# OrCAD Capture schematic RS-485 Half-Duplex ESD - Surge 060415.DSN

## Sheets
1 S01 COVER PAGE AND NOTES: note: BART STILLER; note: KRYPTON SOLUTIONS
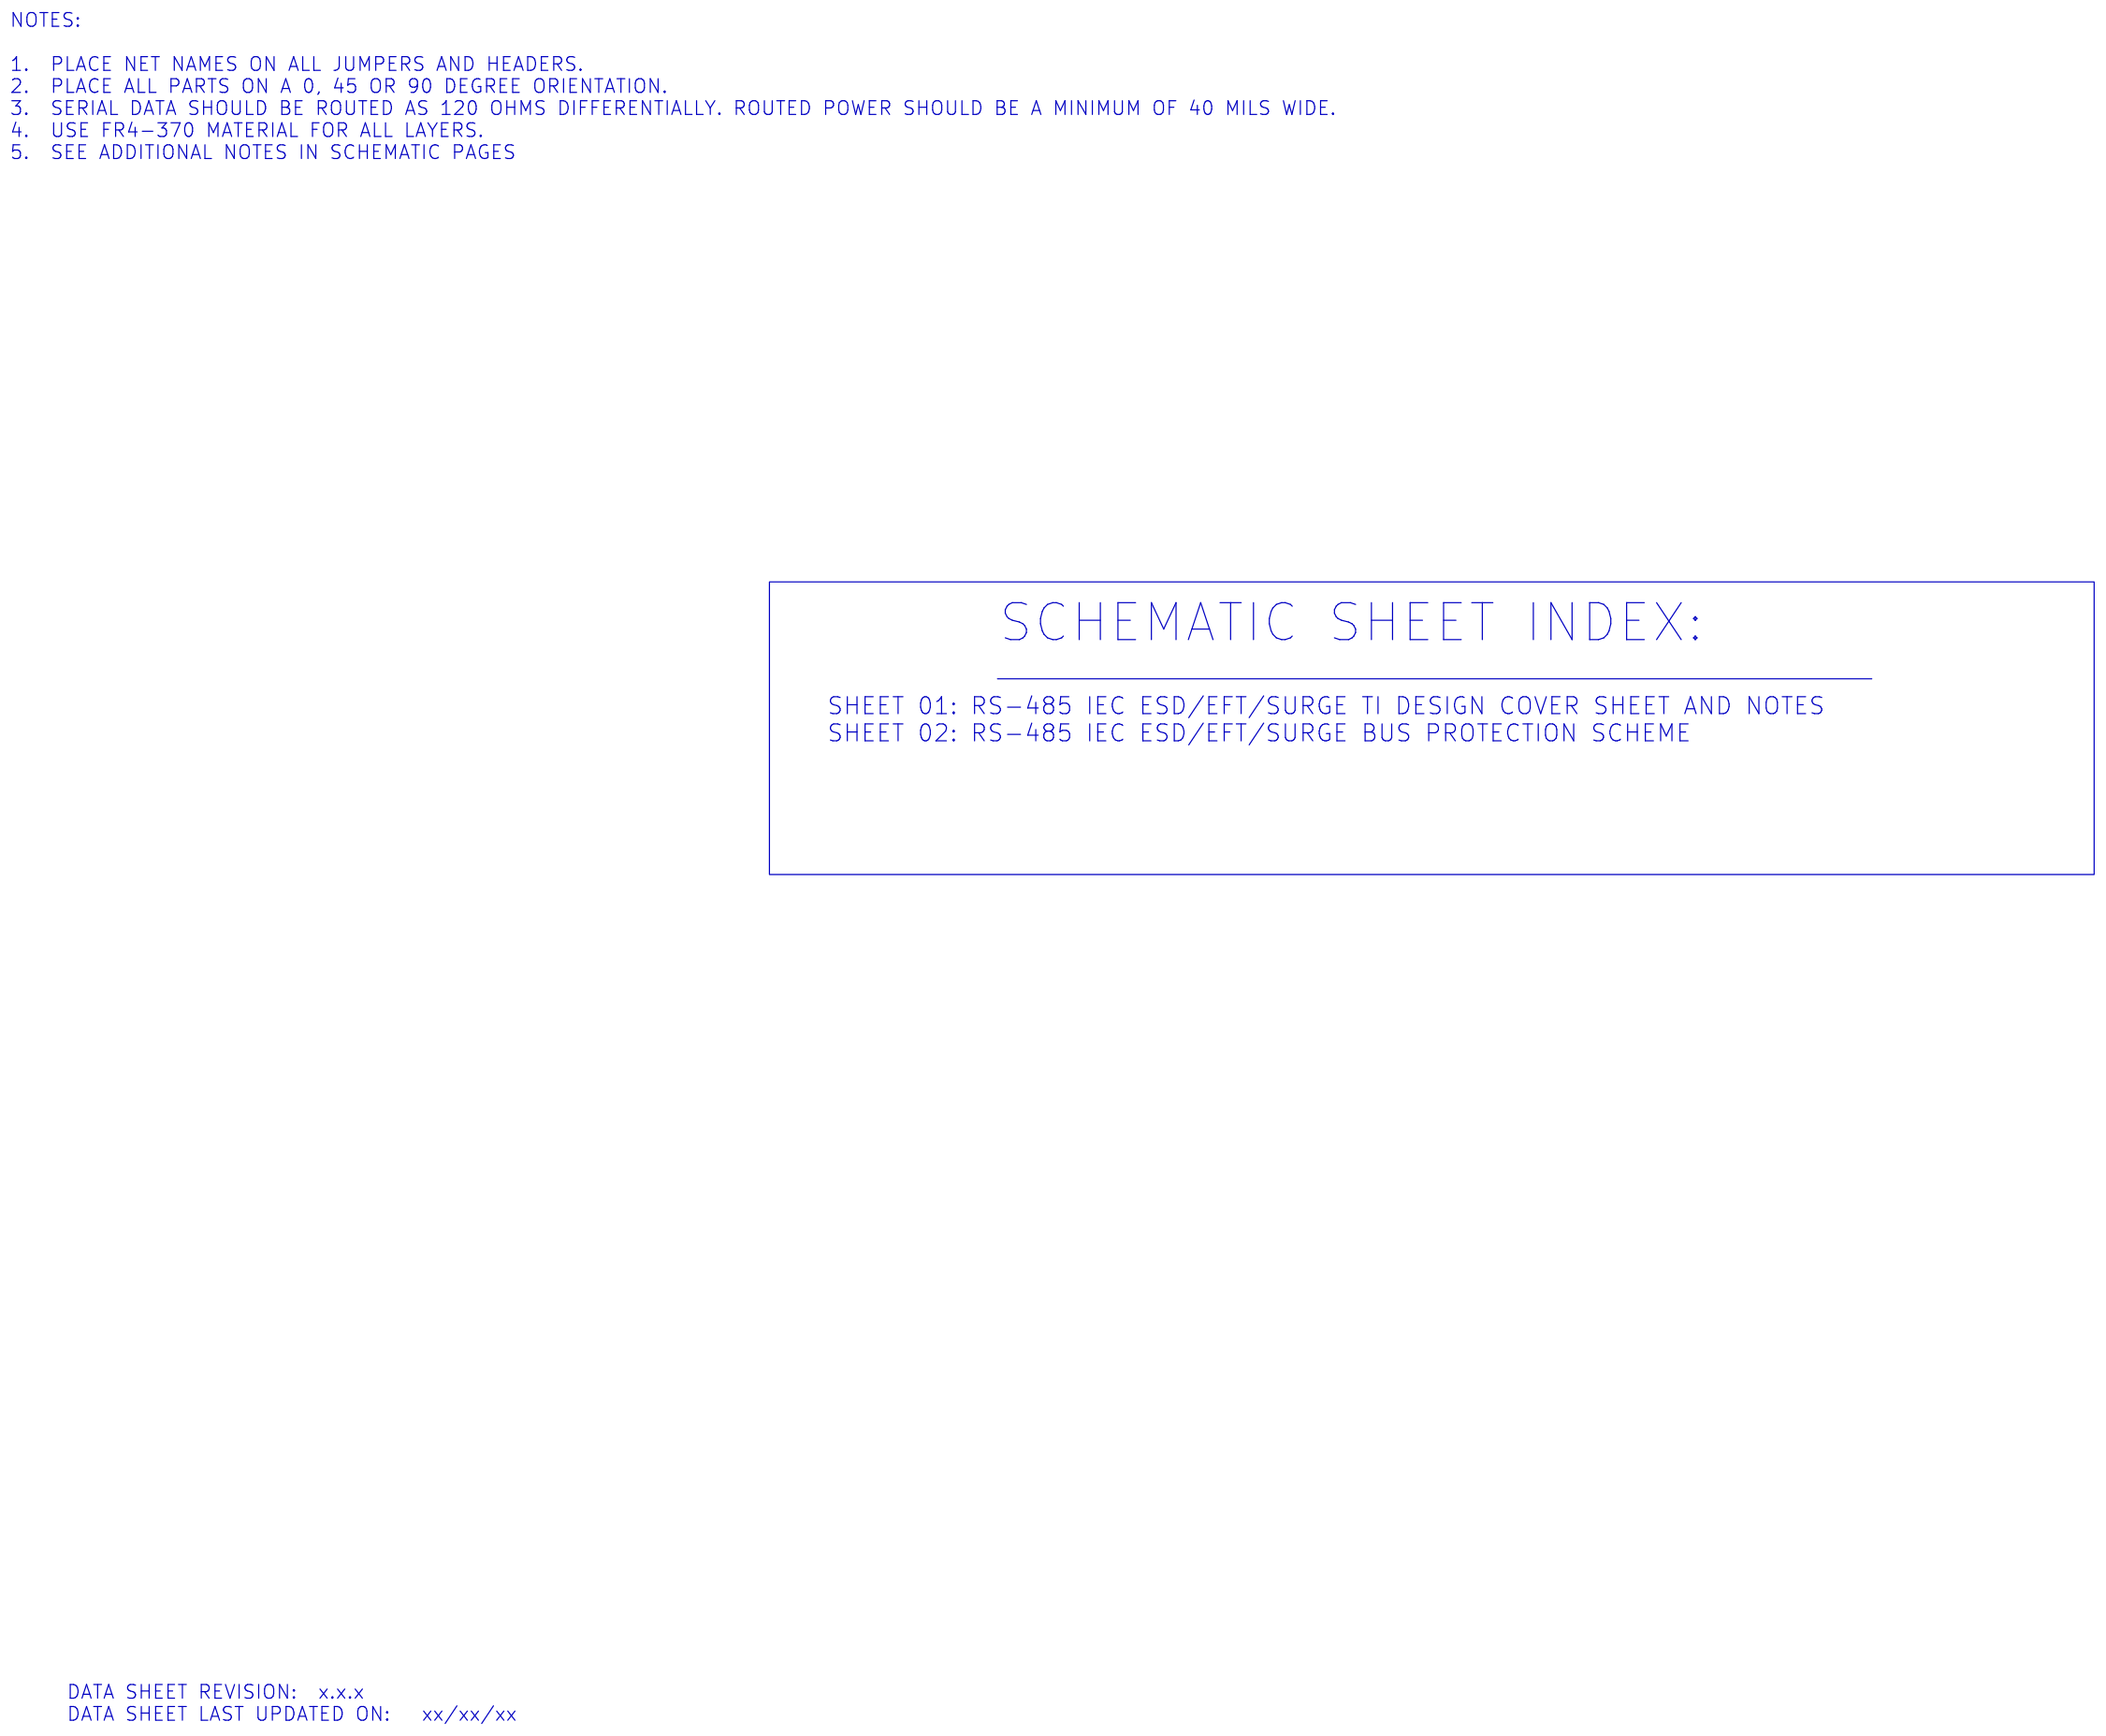
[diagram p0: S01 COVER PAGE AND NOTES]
2 S02 RS-485 SURGE SCHEMATIC: size B
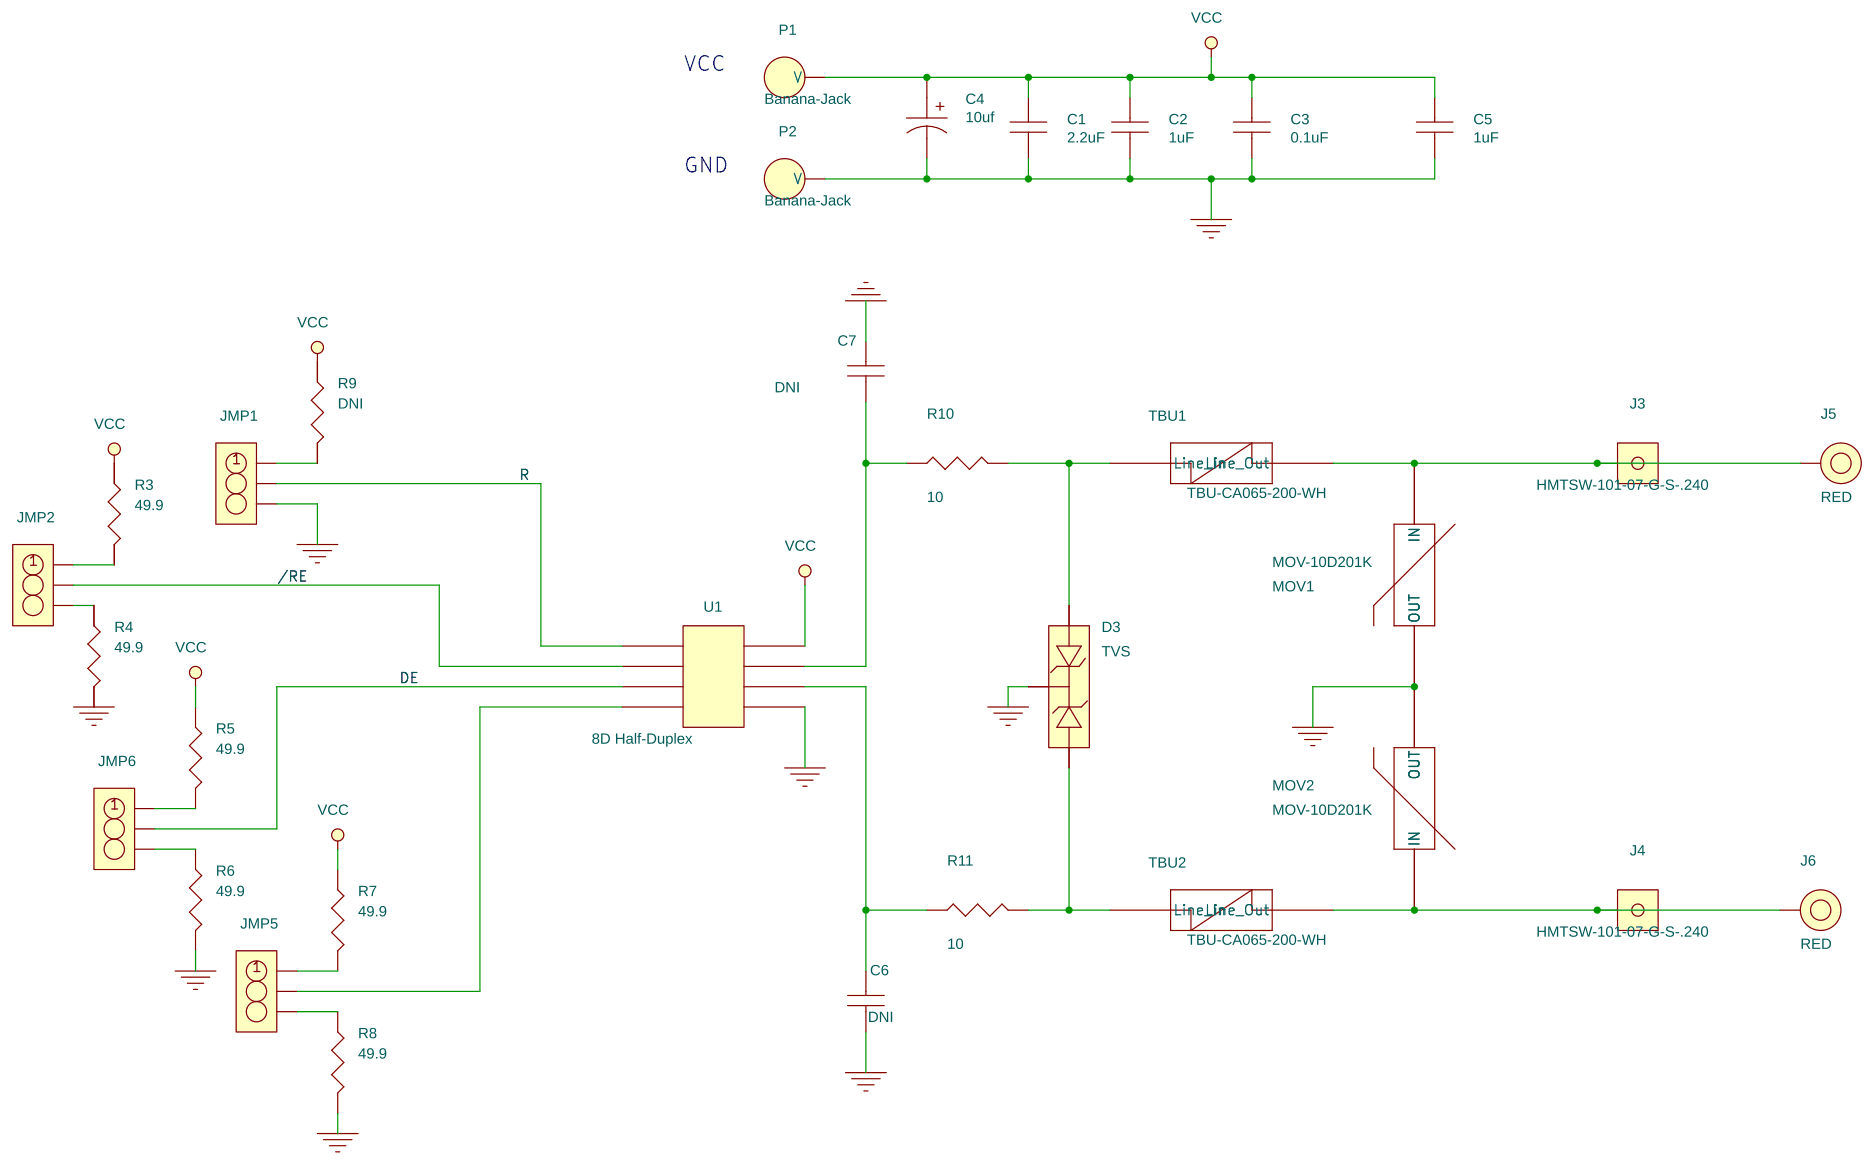
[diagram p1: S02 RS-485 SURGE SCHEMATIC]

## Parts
C1  2.2uF  [1206]
C2  1uF  [0805]
C3  0.1uF  [0603]
C4  10uf  [7343]
C5  1uF  [0402]
C6  DNI  [0603]
C7  DNI  [0603]
D3  TVS  [SOT_23_321]
J3  HMTSW-101-07-G-S-.240  [HDR_THVT_1x1]
J4  HMTSW-101-07-G-S-.240  [HDR_THVT_1x1]
J5  RED  [BANANA_JACK_270mil]
J6  RED  [BANANA_JACK_270mil]
JMP1  Header 3x1  [berg1x3]
JMP2  Header 3x1  [berg1x3]
JMP5  Header 3x1  [berg1x3]
JMP6  Header 3x1  [berg1x3]
MOV1  MOV-10D201K  [VAR_DISC_3p8x12p5mm]
MOV2  MOV-10D201K  [VAR_DISC_3p8x12p5mm]
P1  Banana-Jack  [bjack]
P2  Banana-Jack  [bjack]
R3  49.9  [0603]
R4  49.9  [0603]
R5  49.9  [0603]
R6  49.9  [0603]
R7  49.9  [0603]
R8  49.9  [0603]
R9  DNI  [0603]
R10  10  [0603]
R11  10  [0603]
TBU1  TBU-CA065-200-WH  [DFN_3_157x256]
TBU2  TBU-CA065-200-WH  [DFN_3_157x256]
U1  8D Half-Duplex  [SKT_SK02-0008SOP-QS-05A]

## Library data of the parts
C1 = NPCap1206_1.0uf: TOL: +/- 10%; T_TEMPERATURE: -55C / 125C; VOLTAGE: >50V
C2 = NPCap1206_0.1uf: TOL: +/- 10%; T_TEMPERATURE: -55C / 125C; VOLTAGE: >50V
C3 C5 = NPCap0805_0.01uf: TOL: +/- 10%; T_TEMPERATURE: -55C / 125C; VOLTAGE: >50V
C4 = PCap7343_10uf: TOL: +/- 10%; T_TEMPERATURE: -55C / 125C; VOLTAGE: >50V
C6 C7 = CAP_0603
D3 = Dual_Bi-Directional_TVS_Diode
J3 J4 = HEADER_1x1
J5 J6 = BANANA_JACK_RED_RoHS
JMP1 JMP2 JMP5 JMP6 = Header_3x1
MOV1 MOV2 = MOV-10D201K
P1 P2 = Banana-Jack
R3-R11 = r0603
TBU1 TBU2 = TBU-CA-065-200-WH
U1 = 8_PIN_DEVICE: Manufacturer: Johnstech; PART_NUMBER: JTI-LBD-008SO150-1.27-3291

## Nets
GND1: C1.2 C2.2 C3.2 C4.2 C5.2 C6.2 C7.1 D3.3 JMP1.3 MOV1.2(OUT) MOV2.2(OUT) P2.1(V) R4.2 R6.2 R8.2 U1.5
VCC: C1.1 C2.1 C3.1 C4.1 C5.1 P1.1(V) R3.1 R5.1 R7.1 R9.1 U1.8
/RE: JMP2.2 U1.2
DE: JMP6.2 U1.3
R: JMP1.2 U1.1
N01583: JMP5.2 U1.4
N524936: JMP2.1 R3.2
N525001: JMP2.3 R4.1
N525305: JMP6.1 R5.2
N525367: JMP6.3 R6.1
N525470: JMP5.1 R7.2
N525494: JMP5.3 R8.1
N525767: JMP1.1 R9.2
N527204: D3.2 R11.2 TBU2.1(Line_In)
N527213: D3.1 R10.2 TBU1.1(Line_In)
N527222: C7.2 R10.1 U1.7
N527234: C6.1 R11.1 U1.6
N4743981: J3.1 J5.1 MOV1.1(IN) TBU1.2(Line_Out)
N4743985: J4.1 J6.1 MOV2.1(IN) TBU2.2(Line_Out)

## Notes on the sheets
sheet 1
- NOTES:
  1.  PLACE NET NAMES ON ALL JUMPERS AND HEADERS.
  2.  PLACE ALL PARTS ON A 0, 45 OR 90 DEGREE ORIENTATION.
  3.  SERIAL DATA SHOULD BE ROUTED AS 120 OHMS DIFFERENTIALLY. ROUTED POWER SHOULD BE A MINIMUM OF 40 MILS WIDE.
  4.  USE FR4-370 MATERIAL FOR ALL LAYERS.
  5.  SEE ADDITIONAL NOTES IN SCHEMATIC PAGES
- SCHEMATIC SHEET INDEX:
- SHEET 01: RS-485 IEC ESD/EFT/SURGE TI DESIGN COVER SHEET AND NOTES
  SHEET 02: RS-485 IEC ESD/EFT/SURGE BUS PROTECTION SCHEME
- DATA SHEET REVISION:  x.x.x
  DATA SHEET LAST UPDATED ON:   xx/xx/xx
sheet 2
- VCC
- GND
